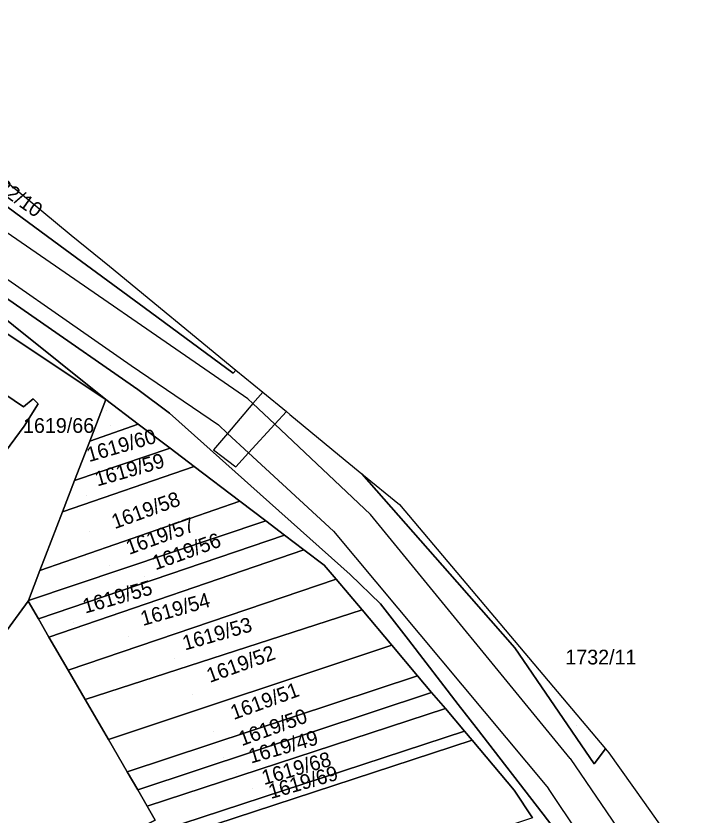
# Model space of a CAD drawing. Extents: x -263943 to -261149, y -1236934 to -1230686.
# Drawn here: x -262071.9 to -261979.8, y -1236532.1 to -1236423.4 of the extents above; entities that cross this region are included whole.
import ezdxf

# ---------------------------------------------------------------- set-up
doc = ezdxf.new("R2010")
doc.units = 0
for name, color, linetype in [('body_kn', 7, 'Continuous'), ('kladpar_druhypozemkov', 7, 'Continuous'), ('kladpar_hranice', 7, 'Continuous'), ('kladpar_parcelnecisla', 7, 'Continuous'), ('kladpar_plochy', 7, 'Continuous'), ('kladpar_sipky', 7, 'Continuous'), ('zappar_hrandruhpozemk', 7, 'Continuous')]:
    doc.layers.add(name, color=color, linetype=linetype)

msp = doc.modelspace()

# ---------------------------------------------------------------- linework, layer by layer
at = {"layer": 'body_kn'}
for p, q in [((-262070.26, -1236448.36), (-262070.26, -1236448.36)), ((-262064.39, -1236453.17), (-262064.39, -1236453.17)), ((-262065.91, -1236454.63), (-262065.91, -1236454.63)), ((-262059.2, -1236457.42), (-262059.2, -1236457.42)), ((-262054.5, -1236463.02), (-262054.5, -1236463.02)), ((-262056.24, -1236470.9), (-262056.24, -1236470.9)), ((-262042.02, -1236471.53), (-262042.02, -1236471.53)), ((-262042.4, -1236471.93), (-262042.4, -1236471.93)), ((-262055.36, -1236474.18), (-262055.36, -1236474.18)), ((-262038.38, -1236474.53), (-262038.38, -1236474.53)), ((-262038.38, -1236474.53), (-262038.38, -1236474.53)), ((-262069.56, -1236475.41), (-262069.56, -1236475.41)), ((-262059.68, -1236475.52), (-262059.68, -1236475.52)), ((-262040.41, -1236475.42), (-262040.41, -1236475.42)), ((-262070.87, -1236476.52), (-262070.87, -1236476.52)), ((-262070.87, -1236476.52), (-262070.87, -1236476.52)), ((-262068.9, -1236476.12), (-262068.9, -1236476.12)), ((-262039.71, -1236476.08), (-262039.71, -1236476.08)), ((-262039.71, -1236476.08), (-262039.71, -1236476.08)), ((-262051.06, -1236477.36), (-262051.06, -1236477.36)), ((-262035.17, -1236477.16), (-262035.17, -1236477.16)), ((-262034.69, -1236477.56), (-262034.69, -1236477.56)), ((-262070.78, -1236479.12), (-262070.78, -1236479.12)), ((-262055.29, -1236478.85), (-262055.29, -1236478.85)), ((-262055.29, -1236478.85), (-262055.29, -1236478.85)), ((-262044.4, -1236478.98), (-262044.4, -1236478.98)), ((-262036.74, -1236478.88), (-262036.74, -1236478.88)), ((-262043.16, -1236480.12), (-262043.16, -1236480.12)), ((-262061.86, -1236481.17), (-262061.86, -1236481.17)), ((-262061.86, -1236481.17), (-262061.86, -1236481.17)), ((-262050.97, -1236482.13), (-262050.97, -1236482.13)), ((-262045.08, -1236482.36), (-262045.08, -1236482.36)), ((-262040.3, -1236482.76), (-262040.3, -1236482.76)), ((-262040.3, -1236482.76), (-262040.3, -1236482.76)), ((-262027.16, -1236483.74), (-262027.16, -1236483.74)), ((-262047.71, -1236484.6), (-262047.71, -1236484.6)), ((-262042.03, -1236484.66), (-262042.03, -1236484.66)), ((-262024.9, -1236485.6), (-262024.9, -1236485.6)), ((-262063.93, -1236486.54), (-262063.93, -1236486.54)), ((-262063.93, -1236486.54), (-262063.93, -1236486.54)), ((-262038.72, -1236488.37), (-262038.72, -1236488.37)), ((-262041.48, -1236489.33), (-262041.48, -1236489.33)), ((-262019.79, -1236489.8), (-262019.79, -1236489.8)), ((-262065.57, -1236490.78), (-262065.57, -1236490.78)), ((-262065.57, -1236490.78), (-262065.57, -1236490.78)), ((-262037.97, -1236491.99), (-262037.97, -1236491.99)), ((-262023.75, -1236491.13), (-262023.75, -1236491.13)), ((-262023.75, -1236491.13), (-262023.75, -1236491.13)), ((-262035.42, -1236493.93), (-262035.42, -1236493.93)), ((-262028.75, -1236493.41), (-262028.75, -1236493.41)), ((-262028.75, -1236493.41), (-262028.75, -1236493.41)), ((-262032.78, -1236495.93), (-262032.78, -1236495.93)), ((-262030.01, -1236498.03), (-262030.01, -1236498.03)), ((-262068.65, -1236498.74), (-262068.65, -1236498.74)), ((-262068.65, -1236498.74), (-262068.65, -1236498.74)), ((-262026.51, -1236499.28), (-262026.51, -1236499.28)), ((-262028.41, -1236499.93), (-262028.41, -1236499.93)), ((-262011.95, -1236500.35), (-262011.95, -1236500.35)), ((-262070.26, -1236502.92), (-262070.26, -1236502.92)), ((-262070.26, -1236502.92), (-262070.26, -1236502.92)), ((-262070.22, -1236502.83), (-262070.22, -1236502.83)), ((-262024.89, -1236504.09), (-262024.89, -1236504.09)), ((-262022.36, -1236503.27), (-262022.36, -1236503.27)), ((-262068.86, -1236505.33), (-262068.86, -1236505.33)), ((-262068.86, -1236505.33), (-262068.86, -1236505.33)), ((-262067.42, -1236507.81), (-262067.42, -1236507.81)), ((-262018.59, -1236508.17), (-262018.59, -1236508.17)), ((-262020.83, -1236508.91), (-262020.83, -1236508.91)), ((-262004.14, -1236509.25), (-262004.14, -1236509.25)), ((-262064.81, -1236512.3), (-262064.81, -1236512.3)), ((-262064.81, -1236512.3), (-262064.81, -1236512.3)), ((-262017.34, -1236513.04), (-262017.34, -1236513.04)), ((-262015.43, -1236515.3), (-262015.43, -1236515.3)), ((-262062.5, -1236516.27), (-262062.5, -1236516.27)), ((-262062.5, -1236516.27), (-262062.5, -1236516.27)), ((-262011.82, -1236516.94), (-262011.82, -1236516.94)), ((-262013.56, -1236517.51), (-262013.56, -1236517.51)), ((-262009.39, -1236520.08), (-262009.39, -1236520.08)), ((-262010.96, -1236520.59), (-262010.96, -1236520.59)), ((-262059.35, -1236521.69), (-262059.35, -1236521.69)), ((-262059.35, -1236521.69), (-262059.35, -1236521.69)), ((-262009.93, -1236521.81), (-262009.93, -1236521.81)), ((-261991.81, -1236522.97), (-261991.81, -1236522.97)), ((-261991.81, -1236522.97), (-261991.81, -1236522.97)), ((-261991.36, -1236523.5), (-261991.36, -1236523.5)), ((-261996.59, -1236524.3), (-261996.59, -1236524.3)), ((-261993.34, -1236525), (-261993.34, -1236525)), ((-262056.8, -1236526.08), (-262056.8, -1236526.08)), ((-262056.8, -1236526.08), (-262056.8, -1236526.08)), ((-262055.35, -1236528.56), (-262055.35, -1236528.56)), ((-262055.35, -1236528.56), (-262055.35, -1236528.56)), ((-262004.2, -1236528.6), (-262004.2, -1236528.6)), ((-261999.57, -1236528.37), (-261999.57, -1236528.37)), ((-262054.06, -1236530.78), (-262054.06, -1236530.78)), ((-261986.55, -1236530.26), (-261986.55, -1236530.26)), ((-262000.3, -1236531.86), (-262000.3, -1236531.86))]:
    msp.add_line(p, q, dxfattribs=at)
at = {"layer": 'kladpar_druhypozemkov'}
for p, q in [((-262059.06, -1236479.05), (-262059.06, -1236479.05)), ((-262057.53, -1236481.1), (-262057.53, -1236481.1)), ((-262062.33, -1236488.6), (-262062.33, -1236488.6)), ((-262061.93, -1236493.4), (-262061.93, -1236493.4)), ((-262059.23, -1236498), (-262059.23, -1236498)), ((-262054.48, -1236499.55), (-262054.48, -1236499.55)), ((-262064.03, -1236505.8), (-262064.03, -1236505.8)), ((-262056.63, -1236507.7), (-262056.63, -1236507.7)), ((-262050.33, -1236510.7), (-262050.33, -1236510.7)), ((-262047.9, -1236515.6), (-262047.9, -1236515.6)), ((-261995.79, -1236519.78), (-261995.79, -1236519.78)), ((-262045.1, -1236520.6), (-262045.1, -1236520.6)), ((-262043.7, -1236524.1), (-262043.7, -1236524.1)), ((-262042, -1236526.3), (-262042, -1236526.3)), ((-262039.8, -1236528.42), (-262039.8, -1236528.42)), ((-262038.82, -1236530.96), (-262038.82, -1236530.96))]:
    msp.add_line(p, q, dxfattribs=at)
at = {"layer": 'kladpar_hranice'}
for points in [[(-262130.74, -1236419.38), (-262126.74, -1236423.83), (-262123, -1236427.98), (-262114.03, -1236438.42), (-262078.67, -1236460.35), (-262059.68, -1236475.52), (-262080.19, -1236461.88), (-262109.38, -1236442.5), (-262116.54, -1236445.19), (-262133.63, -1236451.6), (-262210.45, -1236480.45), (-262252.3, -1236495.97), (-262235.96, -1236539.77), (-262230.02, -1236555.77), (-262257.34, -1236567.36)], [(-261888.92, -1236638.74), (-261904.59, -1236628.26), (-261910.21, -1236624.49), (-261931.19, -1236611.19), (-261937.71, -1236605.8), (-261948.36, -1236596.98), (-261962.84, -1236585.02), (-261973.49, -1236569.45), (-261980.58, -1236559.08), (-261990.29, -1236544.87), (-261993.3, -1236540.93), (-262000.3, -1236531.86), (-262009.39, -1236520.08), (-262011.82, -1236516.94), (-262018.59, -1236508.17), (-262022.36, -1236503.27), (-262026.51, -1236499.28), (-262038.72, -1236488.37), (-262051.06, -1236477.36), (-262055.36, -1236474.18), (-262083.03, -1236454.97), (-262101.17, -1236442.04), (-262126.74, -1236423.83)], [(-262001.73, -1236532.33), (-262004.2, -1236528.6), (-262009.93, -1236521.81), (-262010.96, -1236520.59), (-262013.56, -1236517.51), (-262015.43, -1236515.3), (-262017.34, -1236513.04), (-262020.83, -1236508.91), (-262024.89, -1236504.09), (-262028.41, -1236499.93), (-262030.01, -1236498.03), (-262032.78, -1236495.93), (-262035.42, -1236493.93), (-262037.97, -1236491.99), (-262041.48, -1236489.33), (-262047.71, -1236484.6), (-262050.97, -1236482.13), (-262055.29, -1236478.85), (-262059.68, -1236475.52), (-262078.67, -1236460.35), (-262114.03, -1236438.42), (-262123, -1236427.98), (-262126.74, -1236423.83)], [(-262126.74, -1236423.83), (-262101.17, -1236442.04), (-262083.03, -1236454.97), (-262055.36, -1236474.18), (-262051.06, -1236477.36), (-262038.72, -1236488.37), (-262026.51, -1236499.28), (-262022.36, -1236503.27), (-262018.59, -1236508.17), (-262011.82, -1236516.94), (-262009.39, -1236520.08), (-262000.3, -1236531.86), (-261993.3, -1236540.93), (-261990.29, -1236544.87), (-261980.58, -1236559.08), (-261973.49, -1236569.45), (-261962.84, -1236585.02), (-261948.36, -1236596.98), (-261937.71, -1236605.8), (-261931.19, -1236611.19), (-261910.21, -1236624.49), (-261904.59, -1236628.26), (-261888.92, -1236638.74)], [(-262102.13, -1236427.51), (-262092.87, -1236434.97), (-262089.94, -1236437), (-262083.5, -1236441.69), (-262072.1, -1236450.08), (-262065.91, -1236454.63), (-262054.5, -1236463.02), (-262042.4, -1236471.93), (-262042.02, -1236471.53)], [(-262042.02, -1236471.53), (-262042.4, -1236471.93), (-262054.5, -1236463.02), (-262065.91, -1236454.63), (-262072.1, -1236450.08), (-262083.5, -1236441.69), (-262089.94, -1236437), (-262092.87, -1236434.97), (-262102.13, -1236427.51)], [(-262087.12, -1236434.58), (-262081.12, -1236439.48), (-262070.26, -1236448.36), (-262064.39, -1236453.17), (-262059.2, -1236457.42), (-262042.02, -1236471.53)], [(-262132.09, -1236452.82), (-262117.72, -1236464.17), (-262108.89, -1236470.66), (-262098.44, -1236478.23), (-262085.98, -1236487.36), (-262084.19, -1236488.93), (-262082.6, -1236491.57), (-262082.92, -1236494.29), (-262083.72, -1236496.66), (-262070.78, -1236479.12), (-262068.9, -1236476.12), (-262069.56, -1236475.41), (-262070.87, -1236476.52), (-262093.78, -1236460.98), (-262107.44, -1236451.53), (-262116.54, -1236445.19), (-262109.38, -1236442.5), (-262080.19, -1236461.88), (-262059.68, -1236475.52), (-262061.86, -1236481.17)], [(-262070.87, -1236476.52), (-262069.56, -1236475.41), (-262068.9, -1236476.12), (-262070.78, -1236479.12), (-262083.72, -1236496.66), (-262082.92, -1236494.29), (-262082.6, -1236491.57), (-262084.19, -1236488.93), (-262085.98, -1236487.36), (-262098.44, -1236478.23), (-262108.89, -1236470.66), (-262117.72, -1236464.17), (-262132.09, -1236452.82), (-262133.63, -1236451.6), (-262116.54, -1236445.19), (-262107.44, -1236451.53), (-262093.78, -1236460.98), (-262070.87, -1236476.52)], [(-262042.02, -1236471.53), (-262038.38, -1236474.53), (-262035.17, -1236477.16), (-262034.69, -1236477.56), (-262027.16, -1236483.74), (-262024.9, -1236485.6)], [(-262055.29, -1236478.85), (-262061.86, -1236481.17), (-262059.68, -1236475.52), (-262055.29, -1236478.85)], [(-262061.86, -1236481.17), (-262055.29, -1236478.85), (-262050.97, -1236482.13), (-262063.93, -1236486.54), (-262061.86, -1236481.17)], [(-262061.86, -1236481.17), (-262063.93, -1236486.54), (-262065.57, -1236490.78), (-262068.65, -1236498.74), (-262070.22, -1236502.83), (-262070.26, -1236502.92), (-262099.6, -1236543.02), (-262115.83, -1236564.91), (-262137.52, -1236575.94)], [(-262063.93, -1236486.54), (-262050.97, -1236482.13), (-262047.71, -1236484.6), (-262065.57, -1236490.78), (-262063.93, -1236486.54)], [(-262065.57, -1236490.78), (-262047.71, -1236484.6), (-262041.48, -1236489.33), (-262068.65, -1236498.74), (-262065.57, -1236490.78)], [(-262024.9, -1236485.6), (-262011.95, -1236500.35), (-262004.14, -1236509.25), (-261993.34, -1236525), (-261991.81, -1236522.97)], [(-261991.81, -1236522.97), (-261993.34, -1236525), (-262004.14, -1236509.25), (-262011.95, -1236500.35), (-262024.9, -1236485.6)], [(-262024.9, -1236485.6), (-262019.79, -1236489.8), (-261991.81, -1236522.97)], [(-262068.65, -1236498.74), (-262041.48, -1236489.33), (-262037.97, -1236491.99), (-262070.22, -1236502.83), (-262068.65, -1236498.74)], [(-262070.26, -1236502.92), (-262070.22, -1236502.83), (-262037.97, -1236491.99), (-262035.42, -1236493.93), (-262068.86, -1236505.33), (-262070.26, -1236502.92)], [(-262068.86, -1236505.33), (-262035.42, -1236493.93), (-262032.78, -1236495.93), (-262067.42, -1236507.81), (-262068.86, -1236505.33)], [(-262064.81, -1236512.3), (-262067.42, -1236507.81), (-262032.78, -1236495.93), (-262030.01, -1236498.03), (-262028.41, -1236499.93), (-262064.81, -1236512.3)], [(-262064.81, -1236512.3), (-262028.41, -1236499.93), (-262024.89, -1236504.09), (-262062.5, -1236516.27), (-262064.81, -1236512.3)], [(-262064.81, -1236512.3), (-262062.5, -1236516.27), (-262059.35, -1236521.69), (-262056.8, -1236526.08), (-262055.35, -1236528.56), (-262054.06, -1236530.78), (-262052.97, -1236532.66), (-262063.05, -1236537.66), (-262066.94, -1236539.59), (-262071.7, -1236542.05), (-262115.83, -1236564.91), (-262099.6, -1236543.02), (-262070.26, -1236502.92), (-262068.86, -1236505.33), (-262067.42, -1236507.81), (-262064.81, -1236512.3)], [(-262062.5, -1236516.27), (-262024.89, -1236504.09), (-262020.83, -1236508.91), (-262059.35, -1236521.69), (-262062.5, -1236516.27)], [(-262059.35, -1236521.69), (-262020.83, -1236508.91), (-262017.34, -1236513.04), (-262056.8, -1236526.08), (-262059.35, -1236521.69)], [(-262056.8, -1236526.08), (-262017.34, -1236513.04), (-262015.43, -1236515.3), (-262055.35, -1236528.56), (-262056.8, -1236526.08)], [(-262055.35, -1236528.56), (-262015.43, -1236515.3), (-262013.56, -1236517.51), (-262054.06, -1236530.78), (-262055.35, -1236528.56)], [(-262052.97, -1236532.66), (-262054.06, -1236530.78), (-262013.56, -1236517.51), (-262010.96, -1236520.59), (-262063.05, -1236537.66), (-262052.97, -1236532.66)], [(-262066.94, -1236539.59), (-262063.05, -1236537.66), (-262010.96, -1236520.59), (-262009.93, -1236521.81), (-262071.7, -1236542.05), (-262066.94, -1236539.59)], [(-262144.58, -1236579.59), (-262137.52, -1236575.94), (-262115.83, -1236564.91), (-262071.7, -1236542.05), (-262009.93, -1236521.81), (-262004.2, -1236528.6), (-262001.73, -1236532.33), (-262144.58, -1236579.59)], [(-261991.81, -1236522.97), (-261991.36, -1236523.5), (-261986.55, -1236530.26), (-261982.05, -1236536.59)]]:
    msp.add_lwpolyline(points, dxfattribs=at)
at = {"layer": 'kladpar_plochy'}
for points in [[(-262130.74, -1236419.38), (-262126.74, -1236423.83), (-262123, -1236427.98), (-262114.03, -1236438.42), (-262078.67, -1236460.35), (-262059.68, -1236475.52), (-262080.19, -1236461.88), (-262109.38, -1236442.5), (-262116.54, -1236445.19), (-262133.63, -1236451.6), (-262210.45, -1236480.45), (-262252.3, -1236495.97), (-262235.96, -1236539.77), (-262230.02, -1236555.77), (-262257.34, -1236567.36)], [(-261888.92, -1236638.74), (-261904.59, -1236628.26), (-261910.21, -1236624.49), (-261931.19, -1236611.19), (-261937.71, -1236605.8), (-261948.36, -1236596.98), (-261962.84, -1236585.02), (-261973.49, -1236569.45), (-261980.58, -1236559.08), (-261990.29, -1236544.87), (-261993.3, -1236540.93), (-262000.3, -1236531.86), (-262009.39, -1236520.08), (-262011.82, -1236516.94), (-262018.59, -1236508.17), (-262022.36, -1236503.27), (-262026.51, -1236499.28), (-262038.72, -1236488.37), (-262051.06, -1236477.36), (-262055.36, -1236474.18), (-262083.03, -1236454.97), (-262101.17, -1236442.04), (-262126.74, -1236423.83), (-262130.74, -1236419.38)], [(-262110.91, -1236420.54), (-262107.61, -1236428.93), (-262102.13, -1236427.51), (-262092.87, -1236434.97), (-262089.94, -1236437), (-262083.5, -1236441.69), (-262072.1, -1236450.08), (-262065.91, -1236454.63), (-262054.5, -1236463.02), (-262042.4, -1236471.93), (-262042.02, -1236471.53), (-262038.38, -1236474.53), (-262035.17, -1236477.16), (-262034.69, -1236477.56), (-262027.16, -1236483.74), (-262024.9, -1236485.6), (-262011.95, -1236500.35), (-262004.14, -1236509.25), (-261993.34, -1236525), (-261991.81, -1236522.97), (-261991.36, -1236523.5), (-261986.55, -1236530.26), (-261982.05, -1236536.59)], [(-262083.03, -1236454.97), (-262055.36, -1236474.18), (-262051.06, -1236477.36), (-262038.72, -1236488.37), (-262026.51, -1236499.28), (-262022.36, -1236503.27), (-262018.59, -1236508.17), (-262011.82, -1236516.94), (-262009.39, -1236520.08), (-262000.3, -1236531.86), (-261993.3, -1236540.93)], [(-262001.73, -1236532.33), (-262004.2, -1236528.6), (-262009.93, -1236521.81), (-262010.96, -1236520.59), (-262013.56, -1236517.51), (-262015.43, -1236515.3), (-262017.34, -1236513.04), (-262020.83, -1236508.91), (-262024.89, -1236504.09), (-262028.41, -1236499.93), (-262030.01, -1236498.03), (-262032.78, -1236495.93), (-262035.42, -1236493.93), (-262037.97, -1236491.99), (-262041.48, -1236489.33), (-262047.71, -1236484.6), (-262050.97, -1236482.13), (-262055.29, -1236478.85), (-262059.68, -1236475.52), (-262078.67, -1236460.35)], [(-262083.72, -1236496.66), (-262070.78, -1236479.12), (-262068.9, -1236476.12), (-262069.56, -1236475.41), (-262070.87, -1236476.52), (-262093.78, -1236460.98)], [(-262080.19, -1236461.88), (-262059.68, -1236475.52), (-262061.86, -1236481.17), (-262063.93, -1236486.54), (-262065.57, -1236490.78), (-262068.65, -1236498.74), (-262070.22, -1236502.83), (-262070.26, -1236502.92), (-262099.6, -1236543.02)]]:
    msp.add_lwpolyline(points, dxfattribs=at)
for points in [[(-262087.12, -1236434.58), (-262081.12, -1236439.48), (-262070.26, -1236448.36), (-262064.39, -1236453.17), (-262059.2, -1236457.42), (-262042.02, -1236471.53), (-262042.4, -1236471.93), (-262054.5, -1236463.02), (-262065.91, -1236454.63), (-262072.1, -1236450.08), (-262083.5, -1236441.69), (-262089.94, -1236437), (-262092.87, -1236434.97), (-262102.13, -1236427.51), (-262097.3, -1236426.25)], [(-262070.87, -1236476.52), (-262069.56, -1236475.41), (-262068.9, -1236476.12), (-262070.78, -1236479.12), (-262083.72, -1236496.66), (-262082.92, -1236494.29), (-262082.6, -1236491.57), (-262084.19, -1236488.93), (-262085.98, -1236487.36), (-262098.44, -1236478.23), (-262108.89, -1236470.66), (-262117.72, -1236464.17), (-262132.09, -1236452.82), (-262133.63, -1236451.6), (-262116.54, -1236445.19), (-262107.44, -1236451.53), (-262093.78, -1236460.98)], [(-262055.29, -1236478.85), (-262061.86, -1236481.17), (-262059.68, -1236475.52)], [(-262061.86, -1236481.17), (-262055.29, -1236478.85), (-262050.97, -1236482.13), (-262063.93, -1236486.54)], [(-262063.93, -1236486.54), (-262050.97, -1236482.13), (-262047.71, -1236484.6), (-262065.57, -1236490.78)], [(-262065.57, -1236490.78), (-262047.71, -1236484.6), (-262041.48, -1236489.33), (-262068.65, -1236498.74)], [(-261991.81, -1236522.97), (-261993.34, -1236525), (-262004.14, -1236509.25), (-262011.95, -1236500.35), (-262024.9, -1236485.6), (-262019.79, -1236489.8)], [(-262068.65, -1236498.74), (-262041.48, -1236489.33), (-262037.97, -1236491.99), (-262070.22, -1236502.83)], [(-262070.26, -1236502.92), (-262070.22, -1236502.83), (-262037.97, -1236491.99), (-262035.42, -1236493.93), (-262068.86, -1236505.33)], [(-262068.86, -1236505.33), (-262035.42, -1236493.93), (-262032.78, -1236495.93), (-262067.42, -1236507.81)], [(-262064.81, -1236512.3), (-262067.42, -1236507.81), (-262032.78, -1236495.93), (-262030.01, -1236498.03), (-262028.41, -1236499.93)], [(-262064.81, -1236512.3), (-262028.41, -1236499.93), (-262024.89, -1236504.09), (-262062.5, -1236516.27)], [(-262064.81, -1236512.3), (-262062.5, -1236516.27), (-262059.35, -1236521.69), (-262056.8, -1236526.08), (-262055.35, -1236528.56), (-262054.06, -1236530.78), (-262052.97, -1236532.66), (-262063.05, -1236537.66), (-262066.94, -1236539.59), (-262071.7, -1236542.05), (-262115.83, -1236564.91), (-262099.6, -1236543.02), (-262070.26, -1236502.92), (-262068.86, -1236505.33), (-262067.42, -1236507.81)], [(-262062.5, -1236516.27), (-262024.89, -1236504.09), (-262020.83, -1236508.91), (-262059.35, -1236521.69)], [(-262059.35, -1236521.69), (-262020.83, -1236508.91), (-262017.34, -1236513.04), (-262056.8, -1236526.08)], [(-262056.8, -1236526.08), (-262017.34, -1236513.04), (-262015.43, -1236515.3), (-262055.35, -1236528.56)], [(-262055.35, -1236528.56), (-262015.43, -1236515.3), (-262013.56, -1236517.51), (-262054.06, -1236530.78)], [(-262052.97, -1236532.66), (-262054.06, -1236530.78), (-262013.56, -1236517.51), (-262010.96, -1236520.59), (-262063.05, -1236537.66)], [(-262066.94, -1236539.59), (-262063.05, -1236537.66), (-262010.96, -1236520.59), (-262009.93, -1236521.81), (-262071.7, -1236542.05)], [(-262144.58, -1236579.59), (-262137.52, -1236575.94), (-262115.83, -1236564.91), (-262071.7, -1236542.05), (-262009.93, -1236521.81), (-262004.2, -1236528.6), (-262001.73, -1236532.33)]]:
    msp.add_lwpolyline(points, close=True, dxfattribs=at)
at = {"layer": 'kladpar_sipky'}
for p, q in [((-262059.6, -1236476.96), (-262059.6, -1236476.96)), ((-261999.15, -1236514.6), (-261999.15, -1236514.6))]:
    msp.add_line(p, q, dxfattribs=at)
at = {"layer": 'zappar_hrandruhpozemk'}
for p, q in [((-262040.41, -1236475.42), (-262080.09, -1236448.06)), ((-262038.38, -1236474.53), (-262039.71, -1236476.08)), ((-262039.71, -1236476.08), (-262043.16, -1236480.12)), ((-262036.74, -1236478.88), (-262035.17, -1236477.16)), ((-262040.3, -1236482.76), (-262036.74, -1236478.88)), ((-262023.75, -1236491.13), (-262036.74, -1236478.88)), ((-261996.59, -1236524.3), (-262023.75, -1236491.13)), ((-262028.75, -1236493.41), (-261999.57, -1236528.37)), ((-261996.59, -1236524.3), (-261984.76, -1236541.62)), ((-261988.67, -1236544.49), (-261999.57, -1236528.37))]:
    msp.add_line(p, q, dxfattribs=at)
for points in [[(-262081.88, -1236453.06), (-262056.24, -1236470.9), (-262044.4, -1236478.98), (-262043.16, -1236480.12)], [(-262036.74, -1236478.88), (-262039.71, -1236476.08), (-262040.41, -1236475.42)], [(-262043.16, -1236480.12), (-262045.08, -1236482.36), (-262042.03, -1236484.66), (-262040.3, -1236482.76)], [(-262043.16, -1236480.12), (-262040.3, -1236482.76), (-262028.75, -1236493.41)]]:
    msp.add_lwpolyline(points, dxfattribs=at)

# ---------------------------------------------------------------- texts
at = {"layer": 'kladpar_parcelnecisla'}
for s, rotation, p in [('1732/10', 325, (-262077.12, -1236445.34)), ('1619/60', 16, (-262061.98, -1236484.03)), ('1619/59', 16, (-262060.85, -1236487.34)), ('1619/58', 20, (-262058.48, -1236493.14)), ('1619/57', 20, (-262056.53, -1236496.64)), ('1619/56', 20, (-262052.95, -1236498.73)), ('1619/55', 16, (-262062.5, -1236504.61)), ('1619/54', 16, (-262054.65, -1236506.29)), ('1619/53', 16, (-262048.95, -1236509.62)), ('1619/52', 20, (-262045.57, -1236514.03)), ('1619/51', 20, (-262042.32, -1236519.06)), ('1619/50', 20, (-262041.22, -1236522.62)), ('1619/49', 16, (-262039.97, -1236524.98)), ('1619/68', 16, (-262038.19, -1236527.9)), ('1619/69', 16, (-262037.27, -1236529.8))]:
    msp.add_text(s, height=2, rotation=rotation, dxfattribs=at).set_placement(p)
for s, p in [('1619/66', (-262070.95, -1236480.05)), ('1732/11', (-261997.27, -1236511.51))]:
    msp.add_text(s, height=2, dxfattribs=at).set_placement(p)

doc.saveas('drawing.dxf')
